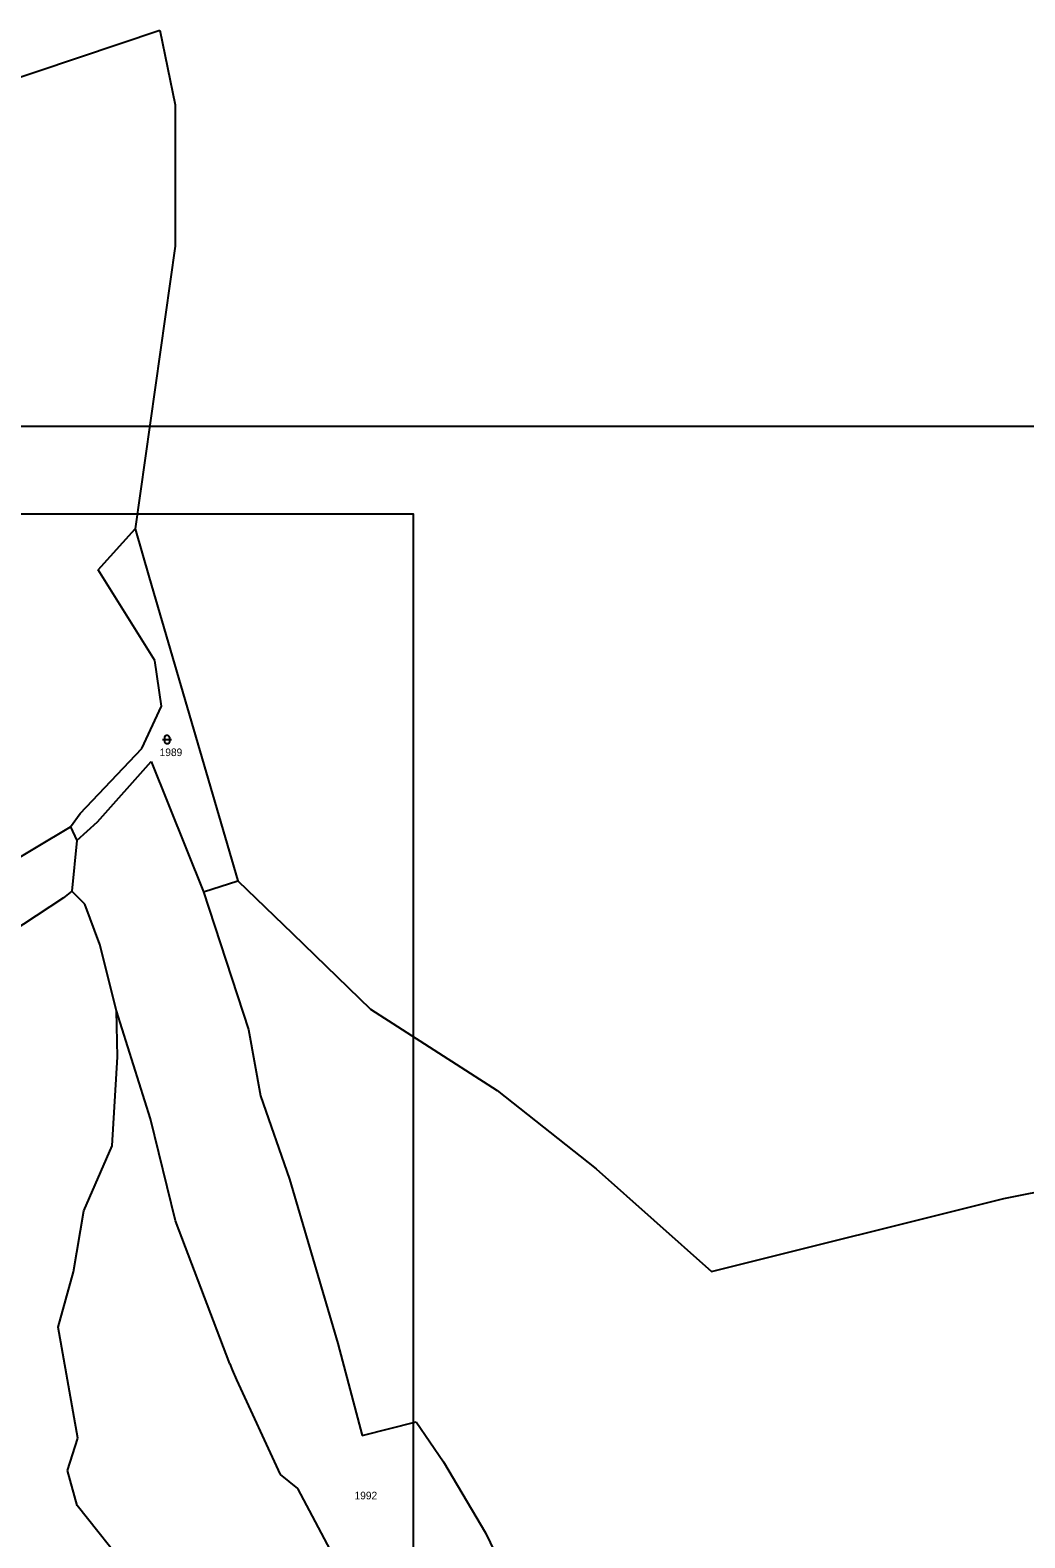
# Model space of a CAD drawing. Extents: x -802857 to -799647, y -1020285 to -1015884.
# Drawn here: x -800948.7 to -800726, y -1017248.9 to -1016911.3 of the extents above; entities that cross this region are included whole.
import ezdxf

# ---------------------------------------------------------------- set-up
doc = ezdxf.new("R2010")
doc.units = 0
for name, color, linetype in [('Default', 7, 'Continuous'), ('KN_HRANICE', 7, 'Continuous'), ('KN_KULTURY', 7, 'Continuous'), ('KN_PARCELY', 7, 'Continuous'), ('LEGENDA', 7, 'Continuous')]:
    doc.layers.add(name, color=color, linetype=linetype)

# ---------------------------------------------------------------- blocks, each defined once
blk = doc.blocks.new('316')
at = {"layer": 'Default'}
for points in [[(-1, 1), (0.27, 1), (1, 1)], [(-0.5, 1.5), (-0.4, 1.79), (-0.15, 1.97), (0.16, 1.97), (0.41, 1.79), (0.51, 1.5), (0.51, 0.5), (0.41, 0.21), (0.16, 0.03), (-0.15, 0.03), (-0.4, 0.21), (-0.5, 0.5), (-0.5, 1.5)]]:
    blk.add_lwpolyline(points, dxfattribs=at)

msp = doc.modelspace()

# ---------------------------------------------------------------- linework, layer by layer
at = {"layer": 'Default'}
msp.add_line((-801875, -1017000), (-800625, -1017000), dxfattribs=at)
at = {"layer": 'KN_HRANICE'}
for p, q in [((-800966.67, -1016927.02), (-800919.72, -1016911.28)), ((-800919.72, -1016911.28), (-800916.22, -1016927.99)), ((-800916.22, -1016927.99), (-800916.27, -1016959.63)), ((-800916.27, -1016959.63), (-800925.21, -1017022.97)), ((-800933.53, -1017032.14), (-800925.21, -1017022.97)), ((-800925.21, -1017022.97), (-800922.04, -1017033.85)), ((-800920.82, -1017052.46), (-800933.53, -1017032.14)), ((-800922.04, -1017033.85), (-800902.21, -1017101.81)), ((-800919.32, -1017062.66), (-800920.82, -1017052.46)), ((-800923.75, -1017072.16), (-800919.32, -1017062.66)), ((-800937.55, -1017086.7), (-800923.75, -1017072.16)), ((-800933.62, -1017088.6), (-800921.62, -1017075.06)), ((-800921.62, -1017075.06), (-800909.89, -1017104.24)), ((-800939.68, -1017089.67), (-800937.55, -1017086.7)), ((-800954.55, -1017098.59), (-800939.68, -1017089.67)), ((-800939.68, -1017089.67), (-800938.24, -1017092.74)), ((-800938.24, -1017092.74), (-800933.62, -1017088.6)), ((-800938.24, -1017092.74), (-800939.36, -1017104.09)), ((-800939.36, -1017104.09), (-800941.26, -1017105.59)), ((-800936.45, -1017107.04), (-800939.36, -1017104.09)), ((-800909.89, -1017104.24), (-800902.21, -1017101.81)), ((-800909.89, -1017104.24), (-800899.86, -1017135.06)), ((-800902.21, -1017101.81), (-800889.98, -1017113.62)), ((-800941.26, -1017105.59), (-801001.86, -1017145.37)), ((-800933.11, -1017116.01), (-800936.45, -1017107.04)), ((-800889.98, -1017113.62), (-800872.5, -1017130.51)), ((-800929.36, -1017130.92), (-800933.11, -1017116.01)), ((-800921.75, -1017155.11), (-800929.36, -1017130.92)), ((-800929.15, -1017141.22), (-800929.36, -1017130.92)), ((-800872.5, -1017130.51), (-800844.16, -1017148.71)), ((-800899.86, -1017135.06), (-800897.14, -1017149.92)), ((-800930.37, -1017161.16), (-800929.15, -1017141.22)), ((-800844.16, -1017148.71), (-800821.95, -1017166.27)), ((-800897.14, -1017149.92), (-800890.63, -1017168.58)), ((-800916.2, -1017177.92), (-800921.75, -1017155.11)), ((-800730.67, -1017172.91), (-800655.34, -1017157.94)), ((-800936.68, -1017175.71), (-800930.37, -1017161.16)), ((-800890.63, -1017168.58), (-800879.8, -1017205.42)), ((-800821.95, -1017166.27), (-800796.12, -1017189.28)), ((-800939.01, -1017189.32), (-800936.68, -1017175.71)), ((-800796.12, -1017189.28), (-800730.67, -1017172.91)), ((-800904.03, -1017209.93), (-800916.2, -1017177.92)), ((-800942.43, -1017201.78), (-800939.01, -1017189.32)), ((-800938.06, -1017226.62), (-800942.43, -1017201.78)), ((-800879.8, -1017205.42), (-800874.4, -1017226.03)), ((-800904.03, -1017209.93), (-800903.5, -1017211.33)), ((-800903.5, -1017211.33), (-800902.5, -1017213.51)), ((-800902.5, -1017213.51), (-800892.76, -1017234.71)), ((-800874.4, -1017226.03), (-800862.25, -1017222.93)), ((-800862.25, -1017222.93), (-800856.18, -1017231.88)), ((-800940.38, -1017233.81), (-800938.06, -1017226.62)), ((-800856.18, -1017231.88), (-800846.78, -1017247.77)), ((-800938.23, -1017241.65), (-800940.38, -1017233.81)), ((-800892.76, -1017234.71), (-800888.89, -1017237.87)), ((-800888.89, -1017237.87), (-800861.07, -1017290.03)), ((-800925.53, -1017257.6), (-800938.23, -1017241.65)), ((-800846.78, -1017247.77), (-800839.54, -1017262.75))]:
    msp.add_line(p, q, dxfattribs=at)
at = {"layer": 'LEGENDA'}
msp.add_lwpolyline([(-801703.84, -1017613.71), (-800862.84, -1017613.71), (-800862.84, -1017019.71), (-801703.84, -1017019.71)], close=True, dxfattribs=at)

# ---------------------------------------------------------------- block references
at = {"layer": 'KN_KULTURY'}
msp.add_blockref('316', (-800918.06, -1017071.15), dxfattribs=at)

# ---------------------------------------------------------------- texts
at = {"layer": 'KN_PARCELY'}
for s, p in [('1989', (-800919.72, -1017073.85)), ('1992', (-800876.07, -1017240.3))]:
    msp.add_text(s, height=1.7, dxfattribs=at).set_placement(p)

doc.saveas('drawing.dxf')
